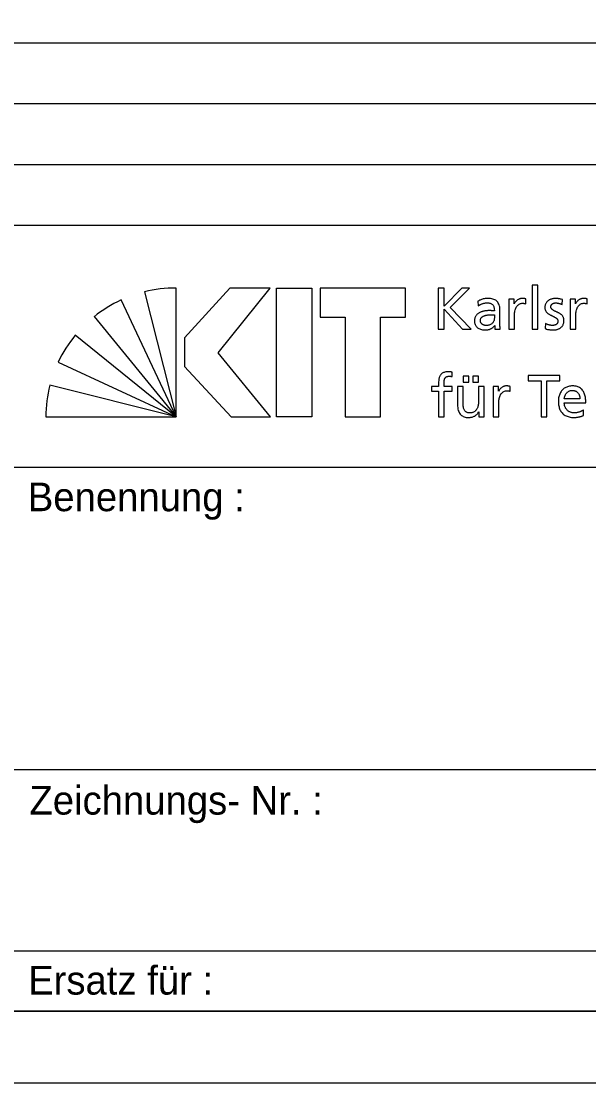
# Model space of a CAD drawing. Extents: x 0 to 420, y 0 to 297.
# Drawn here: x 376.33 to 396.16, y 0 to 37.12 of the extents above; entities that cross this region are included whole.
import ezdxf

# ---------------------------------------------------------------- set-up
doc = ezdxf.new("R2010")
doc.units = 0
doc.layers.add('90_Plankopf', color=7, linetype='Continuous')

msp = doc.modelspace()

# ---------------------------------------------------------------- linework, layer by layer
at = {"layer": '90_Plankopf'}
for p, q in [((329.06, 36.37), (418, 36.37)), ((329.06, 34.245), (418, 34.245)), ((329.06, 32.12), (418, 32.12)), ((329.06, 29.995), (418, 29.995)), ((329.06, 29.995), (418, 29.995)), ((380.637, 27.666), (381.74, 23.293)), ((381.74, 23.293), (381.74, 27.792)), ((390.905, 27.793), (390.905, 26.353)), ((381.74, 23.293), (379.817, 27.376)), ((392.29, 27.331), (392.3, 27.166)), ((393.963, 27.242), (393.963, 27.416)), ((395.228, 27.22), (395.245, 27.389)), ((396.106, 27.242), (396.106, 27.416)), ((378.872, 26.793), (381.74, 23.293)), ((392.865, 26.854), (392.865, 26.761)), ((393.059, 26.559), (393.059, 26.995)), ((394.649, 26.559), (394.638, 26.386)), ((381.74, 23.293), (378.217, 26.143)), ((390.905, 26.353), (391.111, 26.353)), ((391.753, 26.353), (392.054, 26.353)), ((377.62, 25.207), (381.74, 23.293)), ((391.387, 24.696), (391.395, 24.853)), ((381.74, 23.293), (377.329, 24.394)), ((393.413, 24.182), (393.413, 24.356)), ((395.853, 23.92), (395.308, 23.92)), ((395.308, 23.776), (396.059, 23.776)), ((395.979, 23.337), (395.979, 23.53)), ((377.182, 23.293), (381.74, 23.293)), ((376.001, 21.535), (418, 21.535)), ((376.001, 10.96), (418, 10.96)), ((376.001, 4.615), (418, 4.615)), ((418, 2.5), (329.06, 2.5)), ((334.9, 2.5), (418, 2.5)), ((334.9, 2.5), (418, 2.5))]:
    msp.add_line(p, q, dxfattribs=at)
for points in [[(0, 0), (420.5, 0), (420.5, 297), (0, 297)], [(12.5, 294.5), (418, 294.5), (418, 2.5), (12.5, 2.5)], [(385.033, 27.793), (383.618, 27.793), (382.036, 26.049), (382.036, 25.046), (383.669, 23.293), (385.042, 23.293), (383.211, 25.531)], [(386.485, 27.793), (386.485, 23.293), (385.251, 23.293), (385.251, 27.793)], [(386.781, 27.793), (386.781, 26.78), (387.651, 26.78), (387.651, 23.293), (388.885, 23.293), (388.885, 26.78), (389.755, 26.78), (389.755, 27.793)]]:
    msp.add_lwpolyline(points, close=True, dxfattribs=at)
for points in [[(394.19, 26.353), (394.384, 26.353), (394.384, 27.9), (394.19, 27.9), (394.19, 26.353)], [(392.054, 26.353), (391.324, 27.112), (392, 27.793), (391.726, 27.793), (391.111, 27.16), (391.111, 27.793), (390.905, 27.793)], [(393.561, 27.242), (393.557, 27.242), (393.557, 27.405), (393.375, 27.405), (393.375, 26.353), (393.569, 26.353), (393.569, 26.832)], [(395.703, 27.242), (395.699, 27.242), (395.699, 27.405), (395.518, 27.405), (395.518, 26.353), (395.712, 26.353), (395.712, 26.832)], [(391.111, 26.353), (391.111, 27.059), (391.753, 26.353)], [(392.882, 26.489), (392.886, 26.489), (392.886, 26.353), (393.067, 26.353)], [(391.777, 24.713), (391.777, 24.506), (391.971, 24.506), (391.971, 24.713), (391.777, 24.713)], [(392.115, 24.713), (392.115, 24.506), (392.309, 24.506), (392.309, 24.713), (392.115, 24.713)], [(394.495, 23.293), (394.701, 23.293), (394.701, 24.552), (395.149, 24.552), (395.149, 24.733), (394.047, 24.733), (394.047, 24.552), (394.495, 24.552), (394.495, 23.293)], [(390.912, 24.443), (390.912, 24.346), (390.665, 24.346), (390.665, 24.189), (390.912, 24.189), (390.912, 23.293), (391.106, 23.293), (391.106, 24.189), (391.385, 24.189), (391.385, 24.346), (391.106, 24.346), (391.106, 24.459)], [(391.771, 23.801), (391.771, 24.346), (391.577, 24.346), (391.577, 23.72)], [(392.507, 23.293), (392.507, 24.346), (392.313, 24.346), (392.313, 23.859)], [(393.011, 24.182), (393.007, 24.182), (393.007, 24.346), (392.825, 24.346), (392.825, 23.293), (393.019, 23.293), (393.019, 23.772)], [(392.316, 23.46), (392.32, 23.46), (392.32, 23.293), (392.507, 23.293)]]:
    msp.add_lwpolyline(points, dxfattribs=at)
for centre, start, end in [((381.724, 23.028), 89.8053, 103.1895), ((381.831, 23.059), 115.0126, 128.3968), ((381.908, 23.131), 140.7898, 154.174), ((381.946, 23.219), 165.7222, 179.1064)]:
    msp.add_arc(centre, 4.764, start, end, dxfattribs=at)
for points in [[(393.059, 26.995), (393.06, 27.09), (393.045, 27.17), (393.017, 27.235), (392.988, 27.3), (392.942, 27.348), (392.88, 27.381), (392.817, 27.413), (392.736, 27.43), (392.636, 27.43), (392.569, 27.43), (392.507, 27.42), (392.449, 27.402), (392.391, 27.384), (392.338, 27.361), (392.29, 27.331)], [(392.3, 27.166), (392.326, 27.188), (392.356, 27.207), (392.39, 27.223), (392.423, 27.239), (392.458, 27.251), (392.495, 27.26), (392.532, 27.269), (392.568, 27.273), (392.605, 27.273), (392.67, 27.273), (392.721, 27.263), (392.759, 27.243), (392.797, 27.222), (392.824, 27.191), (392.841, 27.151), (392.858, 27.11), (392.865, 27.059), (392.865, 26.999)], [(393.963, 27.416), (393.95, 27.418), (393.937, 27.421), (393.925, 27.423), (393.912, 27.425), (393.899, 27.427), (393.885, 27.428), (393.871, 27.429), (393.854, 27.43), (393.835, 27.43), (393.798, 27.43), (393.761, 27.422), (393.726, 27.406), (393.691, 27.39), (393.659, 27.368), (393.63, 27.339), (393.601, 27.311), (393.578, 27.279), (393.561, 27.242)], [(393.569, 26.832), (393.569, 26.92), (393.581, 26.996), (393.605, 27.06), (393.629, 27.124), (393.662, 27.174), (393.705, 27.208), (393.747, 27.243), (393.798, 27.26), (393.856, 27.261), (393.873, 27.261), (393.89, 27.26), (393.909, 27.257), (393.927, 27.254), (393.945, 27.249), (393.963, 27.242)], [(395.245, 27.389), (395.207, 27.4), (395.169, 27.41), (395.13, 27.418), (395.091, 27.426), (395.049, 27.43), (395.004, 27.43), (394.951, 27.43), (394.903, 27.423), (394.858, 27.41), (394.813, 27.397), (394.774, 27.377), (394.74, 27.35), (394.706, 27.323), (394.68, 27.29), (394.661, 27.249), (394.642, 27.208), (394.632, 27.161), (394.632, 27.106), (394.632, 27.064), (394.641, 27.028), (394.658, 26.997), (394.674, 26.966), (394.695, 26.94), (394.723, 26.917), (394.75, 26.895), (394.779, 26.875), (394.812, 26.857), (394.844, 26.84), (394.876, 26.824), (394.909, 26.809), (394.941, 26.793), (394.971, 26.777), (394.998, 26.761), (395.025, 26.745), (395.047, 26.727), (395.063, 26.706), (395.079, 26.686), (395.088, 26.663), (395.088, 26.636), (395.088, 26.607), (395.082, 26.584), (395.07, 26.564), (395.058, 26.545), (395.042, 26.529), (395.022, 26.518), (395.003, 26.506), (394.982, 26.498), (394.959, 26.493), (394.935, 26.487), (394.912, 26.485), (394.89, 26.485), (394.871, 26.485), (394.847, 26.488), (394.82, 26.493), (394.792, 26.499), (394.763, 26.507), (394.733, 26.518), (394.703, 26.529), (394.675, 26.543), (394.649, 26.559)], [(394.638, 26.386), (394.683, 26.363), (394.73, 26.347), (394.779, 26.339), (394.828, 26.331), (394.877, 26.327), (394.927, 26.328), (394.975, 26.328), (395.02, 26.335), (395.064, 26.348), (395.107, 26.361), (395.147, 26.381), (395.181, 26.408), (395.216, 26.435), (395.243, 26.469), (395.264, 26.51), (395.284, 26.551), (395.294, 26.6), (395.295, 26.656), (395.294, 26.704), (395.286, 26.745), (395.269, 26.778), (395.253, 26.811), (395.231, 26.84), (395.204, 26.863), (395.177, 26.886), (395.147, 26.906), (395.115, 26.922), (395.083, 26.939), (395.05, 26.954), (395.018, 26.968), (394.986, 26.983), (394.956, 26.998), (394.929, 27.013), (394.902, 27.029), (394.88, 27.047), (394.864, 27.068), (394.847, 27.089), (394.839, 27.115), (394.838, 27.145), (394.839, 27.174), (394.848, 27.198), (394.865, 27.217), (394.882, 27.236), (394.904, 27.25), (394.932, 27.259), (394.96, 27.269), (394.991, 27.273), (395.024, 27.273), (395.036, 27.273), (395.051, 27.271), (395.069, 27.269), (395.088, 27.266), (395.107, 27.261), (395.127, 27.256), (395.148, 27.251), (395.167, 27.246), (395.185, 27.239), (395.203, 27.233), (395.217, 27.226), (395.228, 27.22)], [(396.106, 27.416), (396.092, 27.418), (396.079, 27.421), (396.067, 27.423), (396.055, 27.425), (396.041, 27.427), (396.027, 27.428), (396.013, 27.429), (395.997, 27.43), (395.978, 27.43), (395.94, 27.43), (395.904, 27.422), (395.868, 27.406), (395.833, 27.39), (395.801, 27.368), (395.773, 27.339), (395.744, 27.311), (395.721, 27.279), (395.703, 27.242)], [(395.712, 26.832), (395.712, 26.92), (395.724, 26.996), (395.747, 27.06), (395.771, 27.124), (395.804, 27.174), (395.847, 27.208), (395.89, 27.243), (395.94, 27.26), (395.998, 27.261), (396.015, 27.261), (396.033, 27.26), (396.051, 27.257), (396.07, 27.254), (396.088, 27.249), (396.106, 27.242)], [(392.865, 26.999), (392.84, 27), (392.817, 27.001), (392.795, 27.001), (392.773, 27.002), (392.751, 27.003), (392.729, 27.003), (392.708, 27.003), (392.684, 27.003), (392.659, 27.003), (392.618, 27.003), (392.576, 26.999), (392.531, 26.992), (392.487, 26.985), (392.443, 26.973), (392.4, 26.957), (392.358, 26.941), (392.319, 26.919), (392.284, 26.892), (392.25, 26.866), (392.222, 26.833), (392.201, 26.794), (392.181, 26.755), (392.171, 26.709), (392.17, 26.656), (392.171, 26.58), (392.187, 26.518), (392.219, 26.469), (392.252, 26.421), (392.297, 26.385), (392.355, 26.362), (392.413, 26.339), (392.479, 26.328), (392.556, 26.328), (392.6, 26.328), (392.64, 26.334), (392.675, 26.344), (392.71, 26.355), (392.741, 26.368), (392.768, 26.384), (392.795, 26.401), (392.818, 26.419), (392.837, 26.437), (392.855, 26.455), (392.87, 26.472), (392.882, 26.489)], [(392.865, 26.761), (392.865, 26.709), (392.854, 26.661), (392.832, 26.62), (392.81, 26.578), (392.777, 26.546), (392.733, 26.522), (392.69, 26.498), (392.636, 26.485), (392.572, 26.485), (392.55, 26.485), (392.527, 26.489), (392.504, 26.496), (392.481, 26.503), (392.46, 26.514), (392.441, 26.529), (392.422, 26.543), (392.406, 26.561), (392.394, 26.582), (392.383, 26.604), (392.377, 26.628), (392.376, 26.656), (392.377, 26.693), (392.386, 26.724), (392.404, 26.749), (392.422, 26.773), (392.446, 26.793), (392.475, 26.807), (392.503, 26.822), (392.534, 26.833), (392.567, 26.841), (392.6, 26.848), (392.632, 26.853), (392.663, 26.855), (392.694, 26.858), (392.72, 26.859), (392.741, 26.858), (392.762, 26.858), (392.783, 26.858), (392.803, 26.856), (392.824, 26.855), (392.845, 26.855), (392.865, 26.854)], [(393.067, 26.353), (393.066, 26.363), (393.065, 26.377), (393.063, 26.393), (393.062, 26.411), (393.061, 26.433), (393.061, 26.46), (393.06, 26.486), (393.059, 26.52), (393.059, 26.559)], [(391.395, 24.853), (391.375, 24.856), (391.355, 24.859), (391.334, 24.862), (391.312, 24.864), (391.29, 24.866), (391.265, 24.866), (391.194, 24.865), (391.135, 24.855), (391.089, 24.836), (391.043, 24.816), (391.007, 24.787), (390.981, 24.75), (390.955, 24.713), (390.937, 24.668), (390.927, 24.616), (390.917, 24.565), (390.912, 24.507), (390.912, 24.443)], [(391.106, 24.459), (391.106, 24.495), (391.108, 24.528), (391.112, 24.558), (391.116, 24.588), (391.125, 24.615), (391.137, 24.637), (391.15, 24.66), (391.169, 24.677), (391.194, 24.69), (391.219, 24.702), (391.252, 24.709), (391.294, 24.709), (391.311, 24.709), (391.328, 24.708), (391.344, 24.706), (391.361, 24.703), (391.375, 24.7), (391.387, 24.696)], [(393.413, 24.356), (393.4, 24.359), (393.387, 24.361), (393.375, 24.363), (393.363, 24.365), (393.349, 24.367), (393.335, 24.368), (393.321, 24.37), (393.304, 24.37), (393.286, 24.37), (393.248, 24.37), (393.212, 24.362), (393.176, 24.346), (393.141, 24.33), (393.109, 24.308), (393.081, 24.28), (393.052, 24.252), (393.029, 24.219), (393.011, 24.182)], [(393.019, 23.772), (393.02, 23.86), (393.032, 23.937), (393.055, 24.001), (393.079, 24.065), (393.112, 24.114), (393.155, 24.148), (393.198, 24.183), (393.248, 24.201), (393.306, 24.201), (393.323, 24.201), (393.341, 24.2), (393.359, 24.197), (393.378, 24.195), (393.396, 24.19), (393.413, 24.182)], [(396.059, 23.776), (396.06, 23.861), (396.052, 23.94), (396.036, 24.012), (396.02, 24.084), (395.995, 24.146), (395.959, 24.2), (395.923, 24.254), (395.875, 24.295), (395.815, 24.325), (395.756, 24.355), (395.682, 24.37), (395.595, 24.37), (395.52, 24.37), (395.453, 24.357), (395.392, 24.331), (395.332, 24.305), (395.28, 24.269), (395.237, 24.221), (395.194, 24.174), (395.16, 24.118), (395.137, 24.052), (395.114, 23.988), (395.102, 23.916), (395.102, 23.838), (395.102, 23.752), (395.113, 23.674), (395.134, 23.604), (395.156, 23.535), (395.19, 23.475), (395.234, 23.425), (395.279, 23.375), (395.335, 23.336), (395.404, 23.309), (395.473, 23.282), (395.553, 23.269), (395.647, 23.268), (395.704, 23.269), (395.753, 23.273), (395.793, 23.28), (395.834, 23.288), (395.869, 23.297), (395.898, 23.307), (395.928, 23.317), (395.954, 23.327), (395.979, 23.337)], [(395.308, 23.92), (395.312, 23.955), (395.32, 23.989), (395.332, 24.024), (395.344, 24.058), (395.361, 24.089), (395.384, 24.118), (395.406, 24.147), (395.434, 24.17), (395.469, 24.187), (395.503, 24.204), (395.543, 24.213), (395.591, 24.213), (395.633, 24.213), (395.67, 24.206), (395.702, 24.19), (395.735, 24.175), (395.762, 24.154), (395.785, 24.127), (395.807, 24.101), (395.824, 24.069), (395.835, 24.034), (395.847, 23.999), (395.853, 23.961), (395.853, 23.92)], [(392.313, 23.859), (392.313, 23.794), (392.307, 23.736), (392.295, 23.683), (392.282, 23.63), (392.263, 23.584), (392.236, 23.546), (392.21, 23.507), (392.177, 23.478), (392.137, 23.457), (392.096, 23.436), (392.049, 23.426), (391.994, 23.425), (391.938, 23.429), (391.893, 23.444), (391.861, 23.473), (391.828, 23.501), (391.805, 23.542), (391.791, 23.597), (391.777, 23.651), (391.771, 23.719), (391.771, 23.801)], [(395.979, 23.53), (395.967, 23.521), (395.949, 23.51), (395.926, 23.497), (395.903, 23.485), (395.877, 23.474), (395.847, 23.463), (395.817, 23.452), (395.786, 23.443), (395.753, 23.436), (395.72, 23.429), (395.687, 23.426), (395.655, 23.425), (395.608, 23.426), (395.565, 23.434), (395.523, 23.451), (395.482, 23.468), (395.445, 23.492), (395.413, 23.523), (395.38, 23.554), (395.355, 23.59), (395.336, 23.633), (395.318, 23.676), (395.309, 23.724), (395.308, 23.776)], [(391.577, 23.72), (391.577, 23.626), (391.591, 23.545), (391.618, 23.478), (391.646, 23.41), (391.69, 23.359), (391.748, 23.323), (391.806, 23.287), (391.88, 23.269), (391.971, 23.268), (392.02, 23.269), (392.068, 23.276), (392.113, 23.291), (392.158, 23.307), (392.198, 23.329), (392.233, 23.357), (392.268, 23.386), (392.296, 23.42), (392.316, 23.46)]]:
    msp.add_open_spline(points, degree=3, dxfattribs=at)

# ---------------------------------------------------------------- texts
for s, p in [('Benennung :', (376.557, 19.989)), ('Zeichnungs- Nr. :', (376.614, 9.379)), ('Ersatz für :', (376.569, 3.084))]:
    msp.add_text(s, height=1, dxfattribs=at).set_placement(p)

doc.saveas('drawing.dxf')
